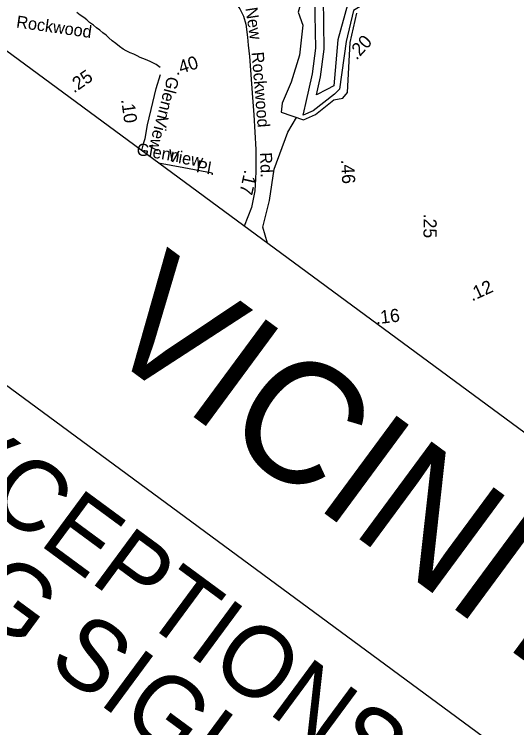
# Model space of a CAD drawing. Extents: x 945666 to 965748, y 644452 to 663300.
# Drawn here: x 952293 to 952913, y 657713 to 658594 of the extents above; entities that cross this region are included whole.
import ezdxf

# ---------------------------------------------------------------- set-up
doc = ezdxf.new("R2010")
doc.units = 0
for name, color, linetype in [('Exist Hydrographic Buffer Line', 7, 'Continuous'), ('Exist Hydrographic Creek Single Shore', 7, 'Continuous'), ('Exist Hydrographic Lake Shore', 7, 'Continuous'), ('Exist Road Secondary Mileage Tenths English Label', 7, 'Continuous'), ('Exist Road Secondary Type 51 Attributed', 7, 'Continuous'), ('Exist Road Secondary Type 51 Label', 7, 'Continuous'), ('Old_Level_1', 7, 'Continuous'), ('Old_Level_38', 7, 'Continuous'), ('Sheet Data Field CELL', 7, 'Continuous')]:
    doc.layers.add(name, color=color, linetype=linetype)

msp = doc.modelspace()

# ---------------------------------------------------------------- linework, layer by layer
at = {"layer": 'Exist Hydrographic Buffer Line'}
for points in [[(952773.65, 658821.7), (952756.76, 658807.04), (952750.66, 658782.92), (952751.46, 658735.3), (952739.42, 658702.93), (952738.71, 658683.4), (952760.16, 658638.21), (952763.97, 658627.07), (952750.89, 658614.68), (952727.29, 658608.41), (952711.7, 658598.86), (952702.4, 658560.26), (952694.06, 658501.49), (952688.27, 658495.53), (952661.76, 658474.64), (952649.47, 658469.33)], [(952649.47, 658469.33), (952650.68, 658474.69), (952652.7, 658483.69), (952660.96, 658520.45), (952664.83, 658552.28), (952663.92, 658614.19)], [(952703.98, 658605.81), (952692.26, 658562.53), (952687.28, 658505.71), (952678.47, 658501.22), (952666.06, 658494.67), (952670.68, 658516.77), (952675.15, 658551.08), (952674.32, 658613.83)]]:
    msp.add_lwpolyline(points, dxfattribs=at)
at = {"layer": 'Exist Hydrographic Creek Single Shore'}
for points in [[(952472.75, 658528.44), (952467.81, 658532.22), (952463.91, 658533.93), (952460.33, 658535.83), (952454.58, 658538.09), (952448.31, 658540.76), (952444.62, 658542.75), (952440.51, 658544.62), (952435.76, 658546.55), (952430.95, 658548.96), (952427.35, 658551.08), (952422.83, 658554.13), (952417.96, 658558.09), (952413.64, 658561.41), (952409.41, 658564.87), (952406.01, 658568.13), (952402.2, 658571.28), (952398.27, 658574.29), (952394.25, 658577.17), (952390.38, 658580.58), (952385.8, 658584.09), (952382.34, 658587.2), (952378.72, 658589.98), (952374.28, 658592.95), (952370.07, 658596.42)], [(952605.22, 658311.35), (952599.44, 658330.9), (952607.92, 658364.17), (952613.68, 658402.75), (952630.57, 658448.37), (952640.97, 658466.71)]]:
    msp.add_lwpolyline(points, dxfattribs=at)
at = {"layer": 'Exist Hydrographic Lake Shore'}
for points in [[(952648.04, 658827.27), (952659.95, 658824.35), (952661.41, 658805.69), (952652.87, 658763.92), (952653.73, 658749.22), (952651.8, 658730.71), (952644.76, 658714.81), (952643.62, 658691.03), (952647.18, 658645.03), (952648.36, 658614.85), (952643.03, 658596.51), (952648.81, 658580.52), (952644.94, 658543.52), (952634.45, 658510.23), (952623.52, 658484.29), (952622.13, 658473.08)], [(952622.13, 658473.08), (952649.71, 658463.77), (952664.46, 658470.15), (952687.1, 658488.24), (952698.42, 658490.29), (952704.26, 658497.62), (952707.48, 658559.13), (952715.56, 658595.38)]]:
    msp.add_lwpolyline(points, dxfattribs=at)
at = {"layer": 'Exist Road Secondary Type 51 Attributed'}
for points in [[(952538.83, 658621.21), (952547.25, 658618.83), (952553.96, 658616.54), (952557.75, 658614.48), (952564.84, 658609.7), (952567.41, 658605.59), (952571.13, 658600.63), (952575.88, 658591.67), (952578.65, 658582.03), (952580.78, 658565.71), (952581.64, 658556.04), (952582.97, 658542.02), (952586.67, 658491.09), (952588.4, 658469.76), (952591.07, 658427.09), (952591.1, 658412.52), (952591.14, 658406.64), (952591.15, 658399.33), (952590.7, 658391.2), (952589.55, 658376.03), (952585.63, 658355.48), (952576.67, 658332.4)], [(952450.23, 658425.65), (952452.76, 658435.77), (952454.26, 658440.5), (952457.22, 658457.6), (952463.97, 658485.22), (952468.06, 658502.38), (952473.47, 658519.7)], [(952470.75, 658410.52), (952502.2, 658404.82), (952536.9, 658398.15)]]:
    msp.add_lwpolyline(points, dxfattribs=at)
at = {"layer": 'Old_Level_1'}
for points in [[(953667.37, 661172.93), (956829.74, 658840.64), (955088.61, 656479.82), (951926.24, 658812.1)], [(951728.89, 658544.51), (954891.26, 656212.23), (955088.61, 656479.82), (951926.24, 658812.1)]]:
    msp.add_lwpolyline(points, close=True, dxfattribs=at)

# ---------------------------------------------------------------- texts
at = {"layer": 'Exist Road Secondary Mileage Tenths English Label'}
for s, rotation, p in [('.20', 47.74817, (952715.36, 658536.9)), ('.40', 18.04742, (952492.76, 658518.57)), ('.25', 34.78384, (952366.5, 658496.24)), ('.10', 277.75046, (952424.64, 658488.67)), ('.46', 272.84878, (952696.14, 658414.34)), ('.17', 257.2235, (952577.15, 658402.61)), ('.25', 269.59344, (952798.07, 658347.74)), ('.12', 24.49675, (952857.91, 658239.31)), ('.16', 6.70704, (952739.49, 658211.07))]:
    msp.add_text(s, height=16.238, rotation=rotation, dxfattribs=at).set_placement(p)
at = {"layer": 'Exist Road Secondary Type 51 Label'}
for s, rotation, p in [('New', 278.57946, (952578, 658601.63)), ('Rockwood', 351.92647, (952294.57, 658577.82)), ('Rockwood', 274.61592, (952585.75, 658547.09)), ('Glenn', 255.59299, (952481.93, 658518.18)), ('View', 256.07052, (952468.93, 658469.79)), ('Glenn', 350.06704, (952442.85, 658420.58)), ('View', 350.06704, (952481.41, 658412.66)), ('Rd.', 272.49262, (952595.86, 658423.23)), ('Pl.', 350.06704, (952516.65, 658399.31))]:
    msp.add_text(s, height=15, rotation=rotation, dxfattribs=at).set_placement(p)
at = {"layer": 'Old_Level_38'}
msp.add_text('VICINITY MAP', height=150, rotation=323.59084, dxfattribs=at).set_placement((952391.64, 658186.9))
at = {"layer": 'Sheet Data Field CELL'}
for s, p in [('1. DESIGN EXCEPTIONS FOR VERTICAL CURVE K VALUE', (951636.01, 658445.97)), (' AND STOPPING SIGHT DISTANCE HAVE BEEN REQUESTED', (951567.93, 658353.65))]:
    msp.add_text(s, height=87.501, rotation=323.59084, dxfattribs=at).set_placement(p)

doc.saveas('drawing.dxf')
